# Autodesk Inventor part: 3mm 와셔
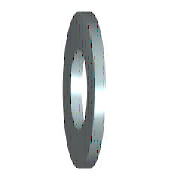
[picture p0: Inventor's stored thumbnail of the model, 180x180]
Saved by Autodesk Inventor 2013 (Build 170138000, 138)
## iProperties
Created: 2012-02
Part Number: 3mm 와셔
Material: 스테인리스강
Description: 평면 와셔 - 대형 시리즈 - 제품 등급 A
Document SubType Name: Modeling
Standard: ISO 7093 A
Designer: mduedu
Standard Revision: First Edition 2000-06-01
Standards Organization: ISO
Language: ko-KR
Size Designation: ST 3 - 140 HV - A
Categories: <MemberInstance><Categories><Category DisplayName="조임쇠" InternalName="e4da775c-781d-43d5-af7c-5136215cf5a6" Mnemonic="FSTN"><Category DisplayName="와셔" InternalN
Density: 8.08 g/cm^3
IsCustomPart: 1
Author: mduedu
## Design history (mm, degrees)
sketch "스케치"
  geometry: C1 r 4.5 at (0, 0); C2 r 1.6 at (0, 0); 1 further point
  constraints: 2 centre point, 2 coincident
  dimensions: "d0" = 3.2 diameter of C2 (= SD1); "d1" = 9 diameter of C1 (= SD2)
extrude "본체" new body sketch "스케치" distance "d2" = 0.8 (= SD); taper "d3" = 0 deg
workaxis "Work Axis1"
workplane "Work Plane1"
sketch "스케치5"
  geometry: 2 further points
  constraints: 1 coincident
body "Solid1"
other parameters: "SD1" = 3.2 [user parameter; used in 1 equation term], "SD2" = 9 [user parameter; used in 1 equation term], "SD" = 0.8 [user parameter; used in 1 equation term], "d4" = 0, "d5" = 0, "d6" = 0, "d7" = 0, "NND" = 3 [user parameter]
